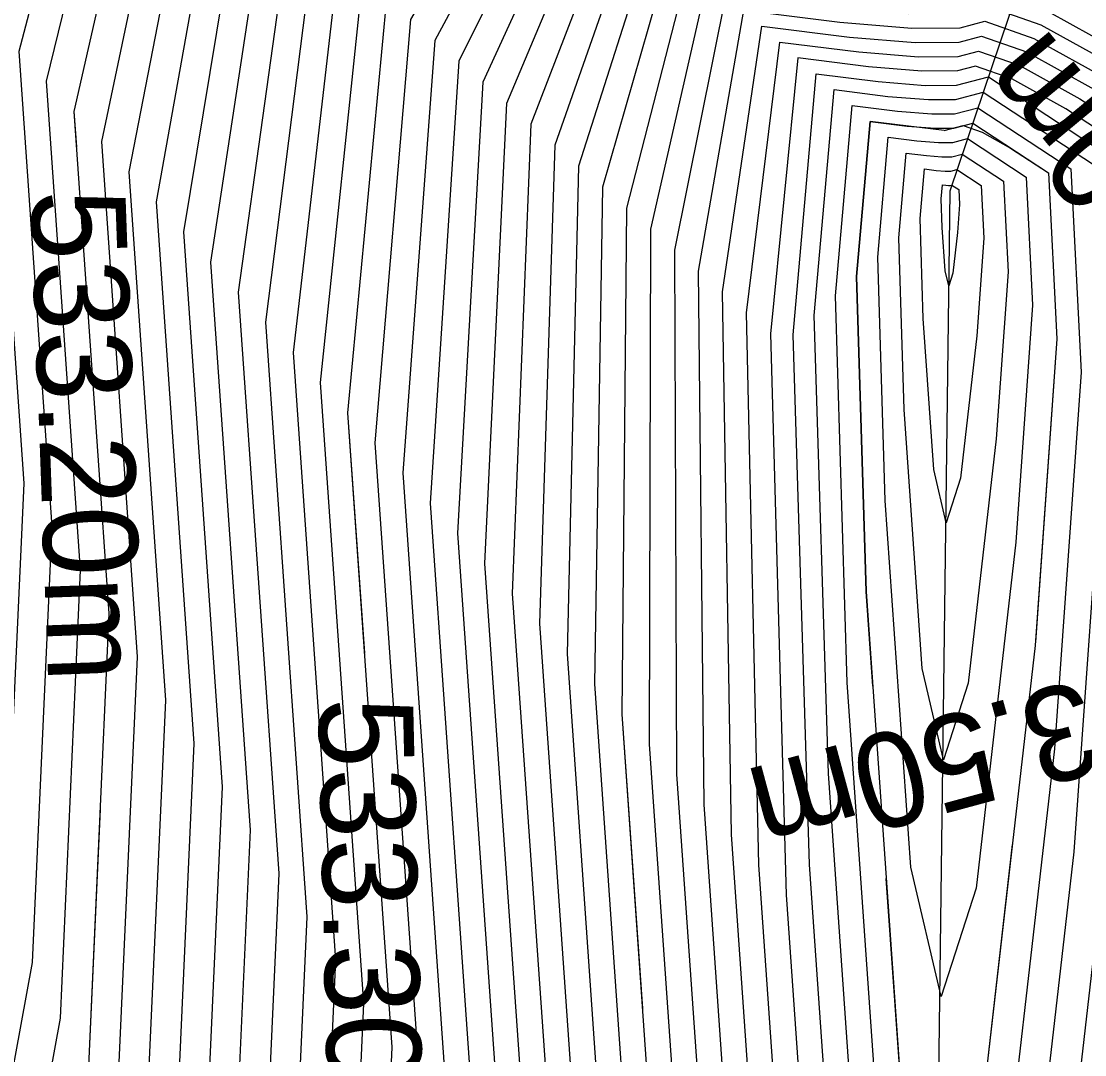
# Model space of a CAD drawing. Extents: x -866683 to -866410, y -1041951 to -1040252.
# Drawn here: x -866452.485 to -866449.115, y -1041929.09 to -1041925.816 of the extents above; entities that cross this region are included whole.
import ezdxf

# ---------------------------------------------------------------- set-up
doc = ezdxf.new("R2010")
doc.units = 0
for name, color, linetype in [('BODY', 7, 'Continuous'), ('BODY_2016', 7, 'Continuous'), ('BREAKLINE', 7, 'Continuous'), ('V-VEDL', 7, 'Continuous'), ('V_po_cm', 7, 'Continuous')]:
    doc.layers.add(name, color=color, linetype=linetype)

msp = doc.modelspace()

# ---------------------------------------------------------------- linework, layer by layer
at = {"layer": 'BREAKLINE'}
msp.add_lwpolyline([(-866430.202, -1041927.282), (-866445.247, -1041913.64), (-866449.543, -1041926.354), (-866449.641, -1041934.033), (-866450.183, -1041936.864), (-866452.267, -1041937.851), (-866451.576, -1041945.087)], dxfattribs=at)
at = {"layer": 'V-VEDL'}
for points in [[(-866449.6778, -1041924.8534), (-866451.5122, -1041924.6245), (-866452.0867, -1041925.0785), (-866452.3185, -1041926.1012), (-866452.2076, -1041927.6924), (-866452.2736, -1041929.1497), (-866452.5165, -1041930.4732), (-866452.9364, -1041931.6628), (-866453.3395, -1041932.2146), (-866453.7258, -1041932.1285), (-866454.0953, -1041931.4045), (-866454.5968, -1041930.9482), (-866455.2304, -1041930.7597), (-866456.7616, -1041930.9181)], [(-866457.0626, -1041933.1405), (-866455.1284, -1041932.9404), (-866454.3281, -1041933.1785), (-866453.6946, -1041933.7549), (-866453.2278, -1041934.6694), (-866452.7398, -1041934.7782), (-866452.2307, -1041934.0812), (-866451.7003, -1041932.5785), (-866451.3935, -1041930.9067), (-866451.3101, -1041929.0659), (-866451.4503, -1041927.056), (-866451.3268, -1041925.7431), (-866450.9398, -1041925.1272), (-866449.6386, -1041925.2896)], [(-866449.5994, -1041925.7259), (-866450.3673, -1041925.63), (-866450.5669, -1041926.4076), (-866450.582, -1041928.0107), (-866450.4127, -1041930.4394), (-866450.4641, -1041932.5242), (-866450.7364, -1041934.2652), (-866451.2295, -1041935.6623), (-866451.5972, -1041936.6715), (-866451.8395, -1041937.2927), (-866451.9565, -1041937.526), (-866451.8502, -1041937.6044), (-866451.5207, -1041937.5279), (-866450.9679, -1041937.2965), (-866450.586, -1041937.3604), (-866450.3749, -1041937.7197), (-866450.2943, -1041939.0287)], [(-866449.5602, -1041926.1621), (-866449.7949, -1041926.1328), (-866449.8381, -1041926.6244), (-866449.8073, -1041927.6224), (-866449.5976, -1041930.6309)], [(-866449.5602, -1041926.1621), (-866449.5002, -1041926.1463), (-866449.4401, -1041926.1673), (-866449.3499, -1041926.2172), (-866449.2297, -1041926.296), (-866449.2038, -1041926.8214), (-866449.2722, -1041927.7935), (-866449.5976, -1041930.6309)]]:
    msp.add_lwpolyline(points, dxfattribs=at)
at = {"layer": 'V_po_cm'}
for points in [[(-866455.261, -1041930.1055), (-866454.6775, -1041930.2791), (-866454.2155, -1041930.6994), (-866453.8751, -1041931.3662), (-866453.5193, -1041931.4455), (-866453.1481, -1041930.9373), (-866452.7614, -1041929.8416), (-866452.5376, -1041928.6226), (-866452.4768, -1041927.2803), (-866452.579, -1041925.8147), (-866452.3147, -1041924.8792), (-866451.684, -1041924.4736), (-866450.6867, -1041924.5981), (-866449.9368, -1041924.6587), (-866449.4342, -1041924.6553), (-866449.1789, -1041924.5881), (-866448.6681, -1041924.7666)], [(-866455.2508, -1041930.3235), (-866454.6506, -1041930.5021), (-866454.1754, -1041930.9344), (-866453.8253, -1041931.6203), (-866453.4594, -1041931.7019), (-866453.0775, -1041931.1792), (-866452.6798, -1041930.0521), (-866452.4496, -1041928.7983), (-866452.3871, -1041927.4177), (-866452.4922, -1041925.9102), (-866452.2387, -1041924.9456), (-866451.6267, -1041924.5239), (-866450.6562, -1041924.645), (-866449.9263, -1041924.704), (-866449.4371, -1041924.7008), (-866449.1886, -1041924.6353), (-866448.6915, -1041924.8091)], [(-866455.2406, -1041930.5416), (-866454.6237, -1041930.7252), (-866454.1354, -1041931.1694), (-866453.7756, -1041931.8744), (-866453.3994, -1041931.9582), (-866453.0069, -1041931.421), (-866452.5981, -1041930.2627), (-866452.3616, -1041928.974), (-866452.2973, -1041927.555), (-866452.4054, -1041926.0057), (-866452.1627, -1041925.0121), (-866451.5695, -1041924.5742), (-866450.6256, -1041924.692), (-866449.9158, -1041924.7493), (-866449.44, -1041924.7462), (-866449.1984, -1041924.6826), (-866448.7149, -1041924.8515)], [(-866449.2354, -1041924.737), (-866449.4429, -1041924.7916), (-866449.9052, -1041924.7947), (-866450.595, -1041924.7389), (-866451.5122, -1041924.6245), (-866452.0867, -1041925.0785), (-866452.3185, -1041926.1012), (-866452.3107, -1041926.213)], [(-866448.7617, -1041924.9364), (-866449.2179, -1041924.777), (-866449.4459, -1041924.837), (-866449.8947, -1041924.84), (-866450.5644, -1041924.7859), (-866451.455, -1041924.6747), (-866452.0107, -1041925.145), (-866452.2317, -1041926.1967), (-866452.1179, -1041927.8297), (-866452.1856, -1041929.3254), (-866452.4349, -1041930.6837), (-866452.8658, -1041931.9047), (-866453.2795, -1041932.4709), (-866453.676, -1041932.3826), (-866454.0552, -1041931.6395), (-866454.57, -1041931.1712), (-866455.2202, -1041930.9777)], [(-866448.7851, -1041924.9789), (-866449.2276, -1041924.8242), (-866449.4488, -1041924.8824), (-866449.8842, -1041924.8853), (-866450.5338, -1041924.8328), (-866451.3977, -1041924.725), (-866451.9348, -1041925.2115), (-866452.1449, -1041926.2921), (-866452.0281, -1041927.9671), (-866452.0976, -1041929.5011), (-866452.3533, -1041930.8942), (-866452.7952, -1041932.1465), (-866453.2195, -1041932.7273), (-866453.6262, -1041932.6367), (-866454.0151, -1041931.8745), (-866454.5431, -1041931.3943), (-866455.21, -1041931.1958)], [(-866448.8085, -1041925.0213), (-866449.2373, -1041924.8714), (-866449.4517, -1041924.9279), (-866449.8736, -1041924.9306), (-866450.5033, -1041924.8798), (-866451.3405, -1041924.7753), (-866451.8588, -1041925.2779), (-866452.058, -1041926.3876), (-866451.9384, -1041928.1044), (-866452.0096, -1041929.6768), (-866452.2717, -1041931.1048), (-866452.7247, -1041932.3883), (-866453.1596, -1041932.9837), (-866453.5764, -1041932.8907), (-866453.9751, -1041932.1096), (-866454.5162, -1041931.6173), (-866455.1998, -1041931.4139)], [(-866448.8318, -1041925.0637), (-866449.2471, -1041924.9186), (-866449.4546, -1041924.9733), (-866449.8631, -1041924.976), (-866450.4727, -1041924.9267), (-866451.2833, -1041924.8256), (-866451.7828, -1041925.3444), (-866451.9712, -1041926.4831), (-866451.8486, -1041928.2418), (-866451.9216, -1041929.8525), (-866452.19, -1041931.3153), (-866452.6541, -1041932.6302), (-866453.0996, -1041933.24), (-866453.5266, -1041933.1448), (-866453.935, -1041932.3446), (-866454.4894, -1041931.8403), (-866455.1896, -1041931.632)], [(-866455.1794, -1041931.85), (-866454.4625, -1041932.0634), (-866453.8949, -1041932.5797), (-866453.4768, -1041933.3989), (-866453.0396, -1041933.4964), (-866452.5835, -1041932.872), (-866452.1084, -1041931.5258), (-866451.8335, -1041930.0282), (-866451.7589, -1041928.3791), (-866451.8844, -1041926.5786), (-866451.7068, -1041925.4108), (-866451.226, -1041924.8759), (-866450.4421, -1041924.9737), (-866449.8526, -1041925.0213), (-866449.4575, -1041925.0187), (-866449.2568, -1041924.9659), (-866448.8552, -1041925.1062)], [(-866448.8786, -1041925.1486), (-866449.2665, -1041925.0131), (-866449.4604, -1041925.0641), (-866449.8421, -1041925.0666), (-866450.4115, -1041925.0206), (-866451.1688, -1041924.9261), (-866451.6308, -1041925.4773), (-866451.7976, -1041926.674), (-866451.6691, -1041928.5165), (-866451.7455, -1041930.2039), (-866452.0268, -1041931.7364), (-866452.513, -1041933.1139), (-866452.9797, -1041933.7527), (-866453.427, -1041933.653), (-866453.8549, -1041932.8147), (-866454.4356, -1041932.2864), (-866455.1692, -1041932.0681)], [(-866455.159, -1041932.2862), (-866454.4087, -1041932.5094), (-866453.8148, -1041933.0497), (-866453.3772, -1041933.9071), (-866452.9197, -1041934.0091), (-866452.4424, -1041933.3557), (-866451.9452, -1041931.9469), (-866451.6575, -1041930.3796), (-866451.5794, -1041928.6538), (-866451.7107, -1041926.7695), (-866451.5548, -1041925.5437), (-866451.1115, -1041924.9764), (-866450.3809, -1041925.0676), (-866449.8315, -1041925.112), (-866449.4633, -1041925.1095), (-866449.2763, -1041925.0603), (-866448.902, -1041925.1911)], [(-866448.9254, -1041925.2335), (-866449.286, -1041925.1075), (-866449.4662, -1041925.1549), (-866449.821, -1041925.1573), (-866450.3503, -1041925.1145), (-866451.0543, -1041925.0267), (-866451.4788, -1041925.6102), (-866451.6239, -1041926.865), (-866451.4896, -1041928.7912), (-866451.5695, -1041930.5553), (-866451.8636, -1041932.1574), (-866452.3718, -1041933.5975), (-866452.8598, -1041934.2654), (-866453.3274, -1041934.1612), (-866453.7747, -1041933.2848), (-866454.3819, -1041932.7325), (-866455.1488, -1041932.5042)], [(-866455.1386, -1041932.7223), (-866454.355, -1041932.9555), (-866453.7347, -1041933.5198), (-866453.2776, -1041934.4153), (-866452.7998, -1041934.5218), (-866452.3012, -1041933.8394), (-866451.782, -1041932.368), (-866451.4815, -1041930.731), (-866451.3999, -1041928.9285), (-866451.5371, -1041926.9605), (-866451.4028, -1041925.6766), (-866450.997, -1041925.077), (-866450.3198, -1041925.1615), (-866449.8105, -1041925.2026), (-866449.4691, -1041925.2004), (-866449.2957, -1041925.1547), (-866448.9488, -1041925.276)], [(-866451.3971, -1041927.8184), (-866451.4503, -1041927.056), (-866451.3268, -1041925.7431), (-866450.9398, -1041925.1272), (-866450.2892, -1041925.2084), (-866449.7999, -1041925.248), (-866449.6265, -1041925.2468)], [(-866455.1182, -1041933.1585), (-866454.3013, -1041933.4016), (-866453.6545, -1041933.9899), (-866453.178, -1041934.9235), (-866452.6799, -1041935.0345), (-866452.1601, -1041934.323), (-866451.6187, -1041932.789), (-866451.3055, -1041931.0824), (-866451.2204, -1041929.2032), (-866451.3634, -1041927.1514), (-866451.2508, -1041925.8095), (-866450.8825, -1041925.1775), (-866450.2586, -1041925.2554), (-866449.7894, -1041925.2933), (-866449.4749, -1041925.2912), (-866449.3152, -1041925.2491), (-866448.9956, -1041925.3608)], [(-866449.019, -1041925.4033), (-866449.3249, -1041925.2964), (-866449.4778, -1041925.3366), (-866449.7789, -1041925.3386), (-866450.228, -1041925.3023), (-866450.8253, -1041925.2278), (-866451.1748, -1041925.876), (-866451.2766, -1041927.2469), (-866451.1306, -1041929.3406), (-866451.2175, -1041931.2581), (-866451.5371, -1041932.9996), (-866452.0895, -1041934.5649), (-866452.6199, -1041935.2909), (-866453.1282, -1041935.1776), (-866453.6144, -1041934.2249), (-866454.2744, -1041933.6246), (-866455.108, -1041933.3765)], [(-866449.0424, -1041925.4457), (-866449.3347, -1041925.3436), (-866449.4808, -1041925.382), (-866449.7683, -1041925.3839), (-866450.1974, -1041925.3493), (-866450.768, -1041925.2781), (-866451.0988, -1041925.9424), (-866451.1898, -1041927.3424), (-866451.0409, -1041929.4779), (-866451.1295, -1041931.4338), (-866451.4555, -1041933.2101), (-866452.019, -1041934.8067), (-866452.5599, -1041935.5472), (-866453.0784, -1041935.4317), (-866453.5744, -1041934.46), (-866454.2475, -1041933.8476), (-866455.0978, -1041933.5946)], [(-866449.0658, -1041925.4882), (-866449.3444, -1041925.3908), (-866449.4837, -1041925.4275), (-866449.7578, -1041925.4293), (-866450.1669, -1041925.3962), (-866450.7108, -1041925.3283), (-866451.0228, -1041926.0089), (-866451.1029, -1041927.4379), (-866450.9511, -1041929.6153), (-866451.0414, -1041931.6095), (-866451.3739, -1041933.4206), (-866451.9484, -1041935.0486), (-866452.5, -1041935.8036), (-866453.0286, -1041935.6857), (-866453.5343, -1041934.695), (-866454.2206, -1041934.0707), (-866455.0876, -1041933.8127)], [(-866455.0774, -1041934.0307), (-866454.1938, -1041934.2937), (-866453.4942, -1041934.9301), (-866452.9788, -1041935.9398), (-866452.44, -1041936.06), (-866451.8778, -1041935.2904), (-866451.2923, -1041933.6312), (-866450.9534, -1041931.7852), (-866450.8614, -1041929.7526), (-866451.0161, -1041927.5333), (-866450.9468, -1041926.0753), (-866450.6536, -1041925.3786), (-866450.1363, -1041925.4432), (-866449.7473, -1041925.4746), (-866449.4866, -1041925.4729), (-866449.3541, -1041925.438), (-866449.0892, -1041925.5306)], [(-866449.1126, -1041925.5731), (-866449.3639, -1041925.4852), (-866449.4895, -1041925.5183), (-866449.7368, -1041925.5199), (-866450.1057, -1041925.4901), (-866450.5963, -1041925.4289), (-866450.8708, -1041926.1418), (-866450.9293, -1041927.6288), (-866450.7716, -1041929.89), (-866450.8654, -1041931.9609), (-866451.2106, -1041933.8417), (-866451.8073, -1041935.5322), (-866452.3801, -1041936.3163)], [(-866448.7794, -1041925.8129), (-866449.136, -1041925.6155), (-866449.3736, -1041925.5324), (-866449.4924, -1041925.5637), (-866449.7262, -1041925.5653), (-866450.0751, -1041925.5371), (-866450.5391, -1041925.4792), (-866450.7948, -1041926.2083), (-866450.8425, -1041927.7243), (-866450.6819, -1041930.0273), (-866450.7774, -1041932.1366), (-866451.129, -1041934.0522), (-866451.7367, -1041935.7741), (-866452.3201, -1041936.5727)], [(-866448.8233, -1041925.844), (-866449.1594, -1041925.6579), (-866449.3833, -1041925.5797), (-866449.4953, -1041925.6091), (-866449.7157, -1041925.6106), (-866450.0445, -1041925.584), (-866450.4818, -1041925.5295), (-866450.7189, -1041926.2747), (-866450.7556, -1041927.8198), (-866450.5921, -1041930.1647), (-866450.6894, -1041932.3123), (-866451.0474, -1041934.2627), (-866451.6661, -1041936.0159), (-866452.2601, -1041936.829)], [(-866448.8672, -1041925.8751), (-866449.1827, -1041925.7004), (-866449.3931, -1041925.6269), (-866449.4982, -1041925.6546), (-866449.7052, -1041925.6559), (-866450.014, -1041925.631), (-866450.4246, -1041925.5797), (-866450.6429, -1041926.3412), (-866450.6688, -1041927.9153), (-866450.5024, -1041930.302), (-866450.5811, -1041932.4306), (-866450.9049, -1041934.3009), (-866452.0428, -1041937.5251)], [(-866449.7223, -1041925.699), (-866449.9834, -1041925.6779), (-866450.3673, -1041925.63), (-866450.5669, -1041926.4076), (-866450.582, -1041928.0107), (-866450.5169, -1041928.9441)], [(-866448.955, -1041925.9373), (-866449.2295, -1041925.7853), (-866449.4126, -1041925.7213), (-866449.504, -1041925.7454), (-866449.6841, -1041925.7466), (-866449.9528, -1041925.7249), (-866450.3101, -1041925.6803), (-866450.4909, -1041926.4741), (-866450.4951, -1041928.1062), (-866450.3229, -1041930.5767), (-866450.3472, -1041932.6178), (-866450.5679, -1041934.2295), (-866451.4023, -1041936.5939)], [(-866448.9988, -1041925.9684), (-866449.2529, -1041925.8277), (-866449.4223, -1041925.7685), (-866449.5069, -1041925.7908), (-866449.6736, -1041925.7919), (-866449.9222, -1041925.7718), (-866450.2528, -1041925.7306), (-866450.4149, -1041926.5405), (-866450.4083, -1041928.2017), (-866450.2332, -1041930.7141), (-866450.2302, -1041932.7114), (-866450.3994, -1041934.1937), (-866451.0821, -1041936.1282)], [(-866450.7619, -1041935.6626), (-866450.2308, -1041934.158), (-866450.1132, -1041932.8051), (-866450.1434, -1041930.8514), (-866450.3215, -1041928.2972), (-866450.3389, -1041926.607), (-866450.1956, -1041925.7808), (-866449.8916, -1041925.8188), (-866449.663, -1041925.8372), (-866449.5098, -1041925.8362), (-866449.432, -1041925.8157), (-866449.2763, -1041925.8702), (-866449.0427, -1041925.9995)], [(-866450.4416, -1041935.197), (-866450.0623, -1041934.1223), (-866449.9962, -1041932.8987), (-866450.0537, -1041930.9888), (-866450.2347, -1041928.3927), (-866450.2629, -1041926.6734), (-866450.1383, -1041925.8311), (-866449.861, -1041925.8657), (-866449.6525, -1041925.8826), (-866449.5128, -1041925.8816), (-866449.4418, -1041925.863), (-866449.2997, -1041925.9126), (-866449.0866, -1041926.0306)], [(-866450.1214, -1041934.7314), (-866449.8938, -1041934.0866), (-866449.8792, -1041932.9923), (-866449.9639, -1041931.1261), (-866450.1478, -1041928.4881), (-866450.1869, -1041926.7399), (-866450.0811, -1041925.8814), (-866449.8305, -1041925.9127), (-866449.642, -1041925.9279), (-866449.5157, -1041925.9271), (-866449.4515, -1041925.9102), (-866449.3231, -1041925.955), (-866449.1305, -1041926.0617), (-866448.8737, -1041926.2301)], [(-866448.9449, -1041926.2432), (-866449.1744, -1041926.0928), (-866449.3465, -1041925.9975), (-866449.4612, -1041925.9574), (-866449.5186, -1041925.9725), (-866449.6315, -1041925.9732), (-866449.7999, -1041925.9596), (-866450.0239, -1041925.9317), (-866450.1109, -1041926.8063), (-866450.061, -1041928.5836), (-866449.8742, -1041931.2635), (-866449.7623, -1041933.0859), (-866449.7253, -1041934.0509), (-866449.8011, -1041934.2658)], [(-866449.7864, -1041927.9223), (-866449.8073, -1041927.6224), (-866449.8381, -1041926.6244), (-866449.7949, -1041926.1328), (-866449.6776, -1041926.1474), (-866449.5893, -1041926.1545), (-866449.5302, -1041926.1542), (-866449.4701, -1041926.1383), (-866449.2297, -1041926.296), (-866449.2038, -1041926.8214), (-866449.2714, -1041927.7827)], [(-866452.2356, -1041928.3117), (-866452.2736, -1041929.1497), (-866452.5165, -1041930.4732), (-866452.9364, -1041931.6628), (-866453.0597, -1041931.8316)], [(-866449.3445, -1041928.4242), (-866449.4349, -1041929.2122), (-866449.5783, -1041929.6566), (-866449.7025, -1041929.1267), (-866449.7439, -1041928.5324)]]:
    msp.add_lwpolyline(points, dxfattribs=at)
for points in [[(-866449.4204, -1041925.9913), (-866449.0161, -1041926.2564), (-866448.9725, -1041927.1401), (-866449.0875, -1041928.775), (-866449.3612, -1041931.161), (-866449.6024, -1041931.9084), (-866449.8112, -1041931.0171), (-866449.9875, -1041928.4872), (-866450.0394, -1041926.8088), (-866449.9666, -1041925.9819), (-866449.7693, -1041926.0066), (-866449.6209, -1041926.0186), (-866449.5215, -1041926.0179)], [(-866449.437, -1041926.0403), (-866449.0873, -1041926.2696), (-866449.0496, -1041927.0339), (-866449.1491, -1041928.4478), (-866449.3857, -1041930.5114), (-866449.5944, -1041931.1578), (-866449.7749, -1041930.387), (-866449.9275, -1041928.1989), (-866449.9723, -1041926.7474), (-866449.9094, -1041926.0322), (-866449.7387, -1041926.0535), (-866449.6104, -1041926.0639), (-866449.5244, -1041926.0633)], [(-866449.4536, -1041926.0893), (-866449.1585, -1041926.2828), (-866449.1267, -1041926.9277), (-866449.2106, -1041928.1207), (-866449.4103, -1041929.8618), (-866449.5863, -1041930.4072), (-866449.7387, -1041929.7568), (-866449.8674, -1041927.9107), (-866449.9052, -1041926.6859), (-866449.8521, -1041926.0825), (-866449.7081, -1041926.1005), (-866449.5999, -1041926.1092), (-866449.5273, -1041926.1087)], [(-866449.4867, -1041926.1874), (-866449.3009, -1041926.3092), (-866449.2809, -1041926.7152), (-866449.3337, -1041927.4663), (-866449.4595, -1041928.5626), (-866449.5703, -1041928.906), (-866449.6662, -1041928.4965), (-866449.7473, -1041927.3341), (-866449.7711, -1041926.563), (-866449.7376, -1041926.1831), (-866449.647, -1041926.1944), (-866449.5788, -1041926.1999), (-866449.5331, -1041926.1996)], [(-866449.5033, -1041926.2364), (-866449.3721, -1041926.3224), (-866449.358, -1041926.609), (-866449.3953, -1041927.1392), (-866449.484, -1041927.913), (-866449.5623, -1041928.1554), (-866449.63, -1041927.8664), (-866449.6872, -1041927.0459), (-866449.704, -1041926.5015), (-866449.6804, -1041926.2333), (-866449.6164, -1041926.2413), (-866449.5683, -1041926.2452), (-866449.536, -1041926.245)], [(-866449.5198, -1041926.2854), (-866449.4433, -1041926.3355), (-866449.4351, -1041926.5027), (-866449.4568, -1041926.812), (-866449.5086, -1041927.2634), (-866449.5542, -1041927.4048), (-866449.5937, -1041927.2362), (-866449.6271, -1041926.7576), (-866449.6369, -1041926.44), (-866449.6231, -1041926.2836), (-866449.5858, -1041926.2883), (-866449.5577, -1041926.2905), (-866449.5389, -1041926.2904)], [(-866449.5364, -1041926.3344), (-866449.5145, -1041926.3487), (-866449.5122, -1041926.3965), (-866449.5184, -1041926.4849), (-866449.5332, -1041926.6138), (-866449.5462, -1041926.6542), (-866449.5575, -1041926.6061), (-866449.567, -1041926.4693), (-866449.5698, -1041926.3786), (-866449.5659, -1041926.3339), (-866449.5552, -1041926.3352), (-866449.5472, -1041926.3359), (-866449.5418, -1041926.3358)]]:
    msp.add_lwpolyline(points, close=True, dxfattribs=at)

# ---------------------------------------------------------------- texts
at = {"layer": 'BODY'}
msp.add_text('+', height=0.001, rotation=360, dxfattribs=at).set_placement((-866449.543, -1041926.354))
at = {"layer": 'BODY_2016'}
msp.add_text('+', height=0.001, rotation=360, dxfattribs=at).set_placement((-866449.543, -1041926.354))
at = {"layer": 'V_po_cm'}
for s, rotation, p in [('533.30m', 153.5533, (-866447.7983, -1041925.9745)), ('533.40m', 129.6267, (-866448.2499, -1041927.031)), ('533.20m', 272.0503, (-866452.4558, -1041926.3533)), ('533.50m', 195.1639, (-866448.6925, -1041927.7813)), ('533.30m', 271.321, (-866451.5438, -1041927.9609))]:
    msp.add_text(s, height=0.3, rotation=rotation, dxfattribs=at).set_placement(p)

doc.saveas('drawing.dxf')
